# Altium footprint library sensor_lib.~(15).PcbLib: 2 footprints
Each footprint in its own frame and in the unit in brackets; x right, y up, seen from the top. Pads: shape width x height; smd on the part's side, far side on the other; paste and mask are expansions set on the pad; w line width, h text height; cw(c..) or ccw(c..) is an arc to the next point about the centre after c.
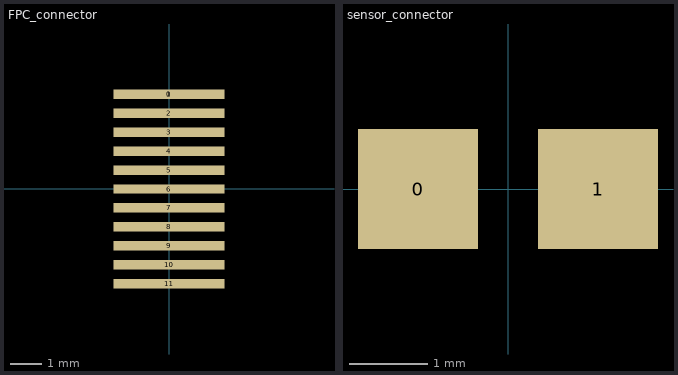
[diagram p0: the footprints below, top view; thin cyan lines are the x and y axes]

## FPC_connector [mm]
pads (12):
  rect 3.5x0.3 smd: 0(0,3) 1(0,3) 2(0,2.4) 3(0,1.8) 4(0,1.2) 5(0,0.6) 6(0,0) 7(0,-0.6) 8(0,-1.2) 9(0,-1.8) 10(0,-2.4) 11(0,-3)

## sensor_connector [mil]
pads (2):
  rect 60x60 smd: 0(-45,0) 1(45,0)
